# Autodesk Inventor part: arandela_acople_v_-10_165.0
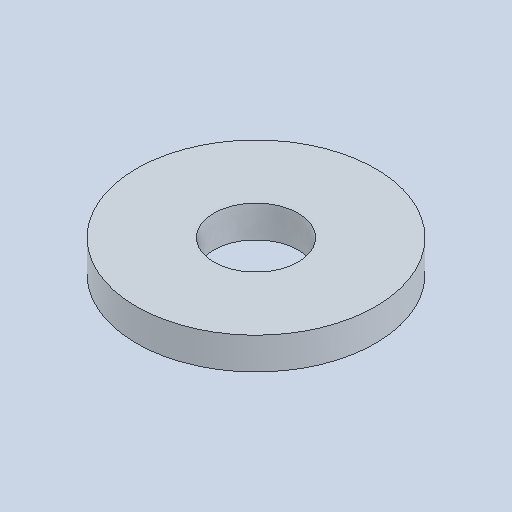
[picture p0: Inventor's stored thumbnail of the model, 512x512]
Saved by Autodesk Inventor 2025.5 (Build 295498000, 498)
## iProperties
Created: 2026-10
Part Number: arandela_acople_v_-10_165.0
Material: Genérico
Document SubType Name: Modeling
Designer: Luis M
Density: 1 g/cm^3
Appearance: Valor por defecto
Author: Luis M
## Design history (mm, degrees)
feature "Base1"
node "Sólido1"
